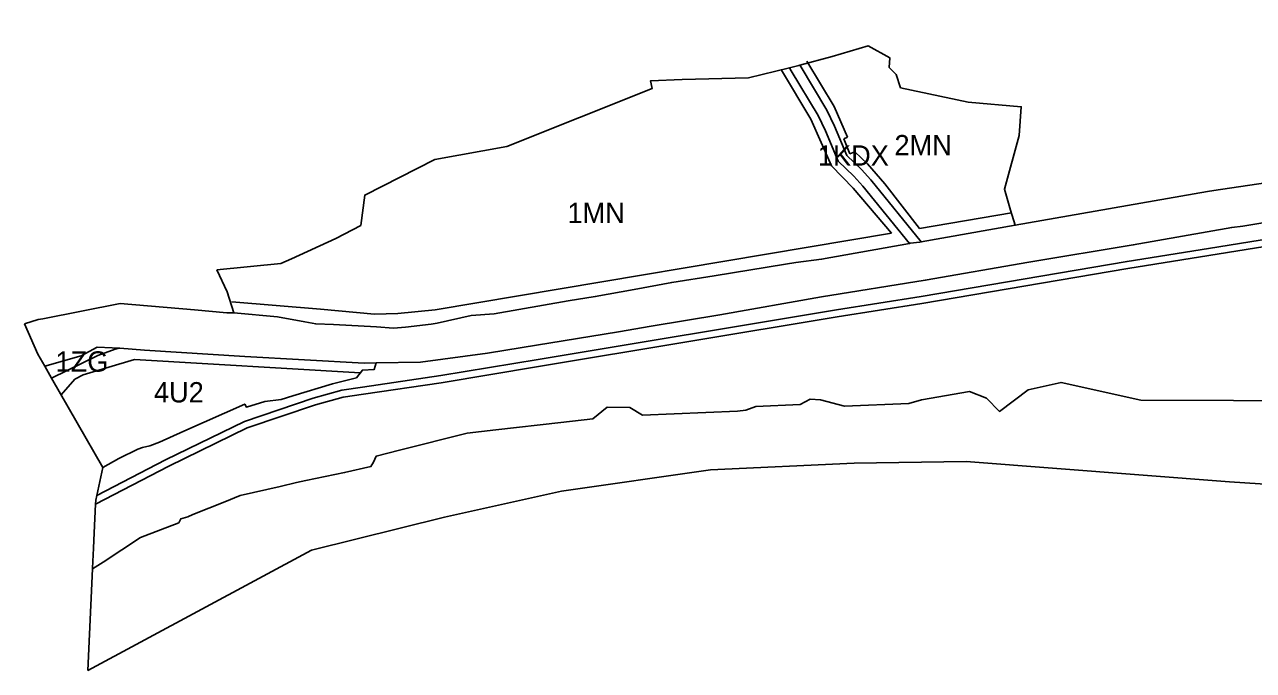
# Model space of a CAD drawing. Extents: x 7417411 to 7420955, y 5545251 to 5546537.
# Drawn here: x 7417411 to 7418015, y 5545778 to 5546096 of the extents above; entities that cross this region are included whole.
import ezdxf

# ---------------------------------------------------------------- set-up
doc = ezdxf.new("R2010")
doc.units = 0
for name, color, linetype in [('linie_rozgraniczajace', 7, 'Continuous'), ('linie_zabudowy_nieprzekraczalne', 7, 'Continuous'), ('oznaczenia_przeznaczen', 7, 'Continuous')]:
    doc.layers.add(name, color=color, linetype=linetype)

msp = doc.modelspace()

# ---------------------------------------------------------------- linework, layer by layer
at = {"layer": 'linie_rozgraniczajace'}
for points in [[(7419155.64, 5546092.88), (7419132.2, 5546095.06), (7419108.06, 5546095.77), (7419052.34, 5546092.98), (7418965.25, 5546085.64), (7418923.69, 5546082.58), (7418720.53, 5546065.71), (7418635.79, 5546059.06), (7418518.89, 5546049.11), (7418468.84, 5546044.86), (7418380.64, 5546038.25), (7418339.35, 5546034.78), (7418278.34, 5546029.66), (7418229.08, 5546023.77), (7418170.55, 5546014.87), (7418106.62, 5546004.07), (7418038.58, 5545993.12), (7417992.79, 5545985.74)], [(7417410.54, 5545948.67), (7417417.18, 5545950.69), (7417419.48, 5545951.05), (7417457.56, 5545958.65), (7417494.16, 5545955.48), (7417510.04, 5545954.1), (7417513.45, 5545954.12), (7417534.92, 5545952.05), (7417548.45, 5545949.56), (7417553.76, 5545948.59), (7417562.54, 5545948.29), (7417583.66, 5545947.09), (7417592.03, 5545946.56), (7417597.82, 5545946.94), (7417610.56, 5545948.49), (7417613.47, 5545948.98), (7417630.23, 5545952.69), (7417641.55, 5545953.57), (7417677.92, 5545959.92), (7417691.25, 5545962.05), (7417710.4, 5545965.6), (7417728.86, 5545969.02), (7417749.65, 5545972.3), (7417784.71, 5545978.01), (7417789.94, 5545978.77), (7417802.5, 5545980.38), (7417845.74, 5545988.16), (7417846.04, 5545988.22), (7417850.83, 5545988.77), (7417851.58, 5545988.91), (7417897.79, 5545997.15), (7417992.36, 5546013.66), (7417995.45, 5546014.19), (7418020.84, 5546017.94)], [(7417446.05, 5545864.17), (7417449.04, 5545878.02), (7417456.86, 5545882.44), (7417466.25, 5545887.04), (7417468.57, 5545887.88), (7417472.21, 5545888.61), (7417476.82, 5545890.51), (7417488.84, 5545895.84), (7417518.8, 5545909.22), (7417519.66, 5545907.75), (7417528.66, 5545910.42), (7417536.8, 5545911.39), (7417542.52, 5545913.26), (7417562.03, 5545919.15), (7417573.73, 5545922.05), (7417576.68, 5545925.93), (7417582.48, 5545926.17), (7417583.45, 5545929.44), (7417605.32, 5545929.77), (7417638.19, 5545934.25), (7417655.2, 5545936.98), (7417702.61, 5545944.78), (7417718.79, 5545947.48), (7417752.47, 5545953.08), (7417802.49, 5545961.87), (7417853.54, 5545970.1), (7417904.49, 5545978.99), (7417955.8, 5545987.41), (7418004.26, 5545996.07), (7418009.65, 5545996.61), (7418060.25, 5546004.97)], [(7418060.25, 5546004.97), (7418009.65, 5545996.61), (7418004.26, 5545996.07), (7417955.8, 5545987.41), (7417904.49, 5545978.99), (7417853.54, 5545970.1), (7417802.49, 5545961.87), (7417752.47, 5545953.08), (7417718.79, 5545947.48), (7417702.61, 5545944.78), (7417655.2, 5545936.98), (7417638.19, 5545934.25), (7417605.32, 5545929.77), (7417583.45, 5545929.44), (7417577.56, 5545929.36), (7417518.79, 5545932.64), (7417469.6, 5545935.76), (7417457.32, 5545936.62)], [(7417443.98, 5545828.11), (7417444, 5545828.43), (7417444.46, 5545838.36), (7417444.81, 5545845.84), (7417445.47, 5545859.93), (7417481.45, 5545878.6), (7417519.97, 5545897.45), (7417553.57, 5545908.76), (7417567.3, 5545912.53), (7417577.19, 5545914.01), (7417615.49, 5545919.71), (7417663.33, 5545927.66), (7417810.17, 5545952.07), (7417851.78, 5545958.63), (7417953.09, 5545975.82), (7417993.05, 5545982.25), (7418038.84, 5545989.62)], [(7417445.47, 5545859.93), (7417445.57, 5545861.95), (7417446.05, 5545864.17), (7417479.87, 5545881.73), (7417518.64, 5545900.69), (7417552.54, 5545912.11), (7417566.58, 5545915.96), (7417576.68, 5545917.47), (7417615.23, 5545923.2), (7417663.08, 5545931.15), (7417809.91, 5545955.56), (7417851.53, 5545962.12), (7417952.83, 5545979.31), (7417992.79, 5545985.74), (7418038.58, 5545993.12)], [(7418038.84, 5545989.62), (7417993.05, 5545982.25), (7417953.09, 5545975.82), (7417851.78, 5545958.63), (7417810.17, 5545952.07), (7417663.33, 5545927.66), (7417615.49, 5545919.71), (7417577.19, 5545914.01), (7417567.3, 5545912.53), (7417553.57, 5545908.76), (7417519.97, 5545897.45), (7417481.45, 5545878.6), (7417445.47, 5545859.93)], [(7417992.79, 5545985.74), (7417952.83, 5545979.31), (7417851.53, 5545962.12), (7417809.91, 5545955.56), (7417663.08, 5545931.15), (7417615.23, 5545923.2), (7417576.68, 5545917.47), (7417566.58, 5545915.96), (7417552.54, 5545912.11), (7417518.64, 5545900.69), (7417479.87, 5545881.73), (7417446.05, 5545864.17)], [(7417457.32, 5545936.62), (7417453.6, 5545936.88), (7417446.29, 5545937.23), (7417438.43, 5545932.93), (7417420.48, 5545927.86), (7417417.13, 5545933.71), (7417410.54, 5545948.67)], [(7417441.65, 5545778.24), (7417443.98, 5545828.11), (7417449.19, 5545831.53), (7417467.55, 5545843.62), (7417477.41, 5545847.4), (7417486.4, 5545850.85), (7417487.33, 5545852.77), (7417490.86, 5545853.83), (7417493.34, 5545854.87), (7417509.05, 5545861.2), (7417516.61, 5545864.26), (7417536.2, 5545868.73), (7417544.34, 5545870.59), (7417548.84, 5545871.61), (7417567.94, 5545875.51), (7417580.87, 5545878.43), (7417582.15, 5545880.58), (7417583.49, 5545883.62), (7417594.96, 5545886.5), (7417628.3, 5545894.87), (7417642.37, 5545896.45), (7417674.32, 5545900.06), (7417689.97, 5545901.94), (7417697.04, 5545907.72), (7417708.22, 5545907.44), (7417714.44, 5545903.73), (7417761.26, 5545905.67), (7417765.33, 5545906.17), (7417770.14, 5545907.99), (7417792.05, 5545908.93), (7417796.92, 5545911.54), (7417802.07, 5545911.31), (7417813.78, 5545908.15), (7417845.4, 5545909.52), (7417851.64, 5545911.33), (7417875.32, 5545915.36), (7417883.65, 5545912.07), (7417890.08, 5545905.56), (7417904.15, 5545916.24), (7417920.31, 5545919.8), (7417959.5, 5545911.19), (7418050.76, 5545910.8)], [(7418050.76, 5545910.8), (7417959.5, 5545911.19), (7417920.31, 5545919.8), (7417904.15, 5545916.24), (7417890.08, 5545905.56), (7417883.65, 5545912.07), (7417875.32, 5545915.36), (7417851.64, 5545911.33), (7417845.4, 5545909.52), (7417813.78, 5545908.15), (7417802.07, 5545911.31), (7417796.92, 5545911.54), (7417792.05, 5545908.93), (7417770.14, 5545907.99), (7417765.33, 5545906.17), (7417761.26, 5545905.67), (7417714.44, 5545903.73), (7417708.22, 5545907.44), (7417697.04, 5545907.72), (7417689.97, 5545901.94), (7417674.32, 5545900.06), (7417642.37, 5545896.45), (7417628.3, 5545894.87), (7417594.96, 5545886.5), (7417583.49, 5545883.62), (7417582.15, 5545880.58), (7417580.87, 5545878.43), (7417567.94, 5545875.51), (7417548.84, 5545871.61), (7417544.34, 5545870.59), (7417536.2, 5545868.73), (7417516.61, 5545864.26), (7417509.05, 5545861.2), (7417493.34, 5545854.87), (7417490.86, 5545853.83), (7417487.33, 5545852.77), (7417486.4, 5545850.85), (7417477.41, 5545847.4), (7417467.55, 5545843.62), (7417449.19, 5545831.53), (7417443.98, 5545828.11)], [(7418425.45, 5545868.58), (7418277.82, 5545871.06), (7418100.66, 5545868.44), (7418055.91, 5545867.57), (7418003.1, 5545871), (7417873.73, 5545880.98), (7417818.63, 5545880.1), (7417747.98, 5545876.79), (7417674.6, 5545866.34), (7417617, 5545853.55), (7417551.59, 5545837.43), (7417441.65, 5545778.24)]]:
    msp.add_lwpolyline(points, dxfattribs=at)
for points in [[(7417791.85, 5546075.81), (7417807.75, 5546080.08), (7417825.48, 5546085.37), (7417836.06, 5546079.47), (7417835.85, 5546074.75), (7417839.25, 5546071.2), (7417841.41, 5546064.72), (7417874.63, 5546057.7), (7417900.74, 5546055.38), (7417899.71, 5546041.24), (7417892.45, 5546014.88), (7417895.53, 5546004.46), (7417897.79, 5545997.15), (7417851.58, 5545988.91), (7417826.71, 5546019.51), (7417822.17, 5546024.59), (7417814.98, 5546031.41), (7417808.91, 5546045.8), (7417805.16, 5546053.67), (7417791.93, 5546075.69)], [(7417505.02, 5545975.12), (7417536.65, 5545978.24), (7417541.79, 5545980.58), (7417563.59, 5545990.52), (7417575.88, 5545997.03), (7417577.88, 5546011.97), (7417612.39, 5546029.46), (7417647.73, 5546035.76), (7417719.16, 5546064.27), (7417718.44, 5546068.17), (7417733.94, 5546068.71), (7417766.53, 5546069.55), (7417786.78, 5546074.55), (7417787.64, 5546073.11), (7417800.87, 5546051.09), (7417804.43, 5546043.54), (7417810.73, 5546028.63), (7417818.44, 5546021.26), (7417822.9, 5546016.26), (7417845.74, 5545988.16), (7417802.5, 5545980.38), (7417789.94, 5545978.77), (7417784.71, 5545978.01), (7417749.65, 5545972.3), (7417728.86, 5545969.02), (7417710.4, 5545965.6), (7417691.25, 5545962.05), (7417677.92, 5545959.92), (7417641.55, 5545953.57), (7417630.23, 5545952.69), (7417613.47, 5545948.98), (7417610.56, 5545948.49), (7417597.82, 5545946.94), (7417592.03, 5545946.56), (7417583.66, 5545947.09), (7417562.54, 5545948.29), (7417553.76, 5545948.59), (7417548.45, 5545949.56), (7417534.92, 5545952.05), (7417513.45, 5545954.12), (7417510.18, 5545964.39)], [(7417786.78, 5546074.55), (7417791.27, 5546075.66), (7417791.85, 5546075.81), (7417791.93, 5546075.69), (7417805.16, 5546053.67), (7417808.91, 5546045.8), (7417814.98, 5546031.41), (7417822.17, 5546024.59), (7417826.71, 5546019.51), (7417851.58, 5545988.91), (7417850.83, 5545988.77), (7417846.04, 5545988.22), (7417845.74, 5545988.16), (7417822.9, 5546016.26), (7417818.44, 5546021.26), (7417810.73, 5546028.63), (7417804.43, 5546043.54), (7417800.87, 5546051.09), (7417787.64, 5546073.11)], [(7417420.48, 5545927.86), (7417438.43, 5545932.93), (7417446.29, 5545937.23), (7417453.6, 5545936.88), (7417457.32, 5545936.62), (7417455.03, 5545936.16), (7417446.65, 5545933.11), (7417423.86, 5545921.96)], [(7417423.86, 5545921.96), (7417446.65, 5545933.11), (7417455.03, 5545936.16), (7417457.32, 5545936.62), (7417469.6, 5545935.76), (7417518.79, 5545932.64), (7417577.56, 5545929.36), (7417583.45, 5545929.44), (7417582.48, 5545926.17), (7417576.68, 5545925.93), (7417573.73, 5545922.05), (7417562.03, 5545919.15), (7417542.52, 5545913.26), (7417536.8, 5545911.39), (7417528.66, 5545910.42), (7417519.66, 5545907.75), (7417518.8, 5545909.22), (7417488.84, 5545895.84), (7417476.82, 5545890.51), (7417472.21, 5545888.61), (7417468.57, 5545887.88), (7417466.25, 5545887.04), (7417456.86, 5545882.44), (7417449.04, 5545878.02)]]:
    msp.add_lwpolyline(points, close=True, dxfattribs=at)
at = {"layer": 'linie_zabudowy_nieprzekraczalne'}
for points in [[(7417818.12, 5546015.42), (7417807.36, 5546026.34), (7417797.31, 5546049.25), (7417782.81, 5546073.39)], [(7417795.36, 5546077.75), (7417808.72, 5546055.51), (7417815.35, 5546040.48)], [(7417815.35, 5546040.48), (7417813.44, 5546039.55)], [(7417813.44, 5546039.55), (7417816.47, 5546032.27)], [(7417816.47, 5546032.27), (7417818.89, 5546033.22)], [(7417818.87, 5546033.23), (7417825.06, 5546027.36), (7417833.57, 5546017.53)], [(7417836.97, 5545993.28), (7417818.12, 5546015.42)], [(7417833.57, 5546017.53), (7417850.63, 5545995.54)], [(7417850.63, 5545995.54), (7417895.9, 5546003.2)], [(7417512.53, 5545959.49), (7417556.08, 5545955.87), (7417582.62, 5545953.35), (7417594.08, 5545953.65), (7417612.41, 5545955.48), (7417836.97, 5545993.28)], [(7417575.56, 5545924.47), (7417464.53, 5545931.06), (7417439.4, 5545923.61), (7417435.3, 5545921.43), (7417428.58, 5545913.72)]]:
    msp.add_lwpolyline(points, dxfattribs=at)

# ---------------------------------------------------------------- texts
at = {"layer": 'oznaczenia_przeznaczen'}
for s, p in [('1KDX', (7417800.7, 5546026.4)), ('2MN', (7417838.38, 5546031.49)), ('1MN', (7417677.56, 5545998.18)), ('1ZG', (7417425.76, 5545925.12)), ('4U2', (7417474.16, 5545909.99))]:
    msp.add_text(s, height=10, dxfattribs=at).set_placement(p)

doc.saveas('drawing.dxf')
